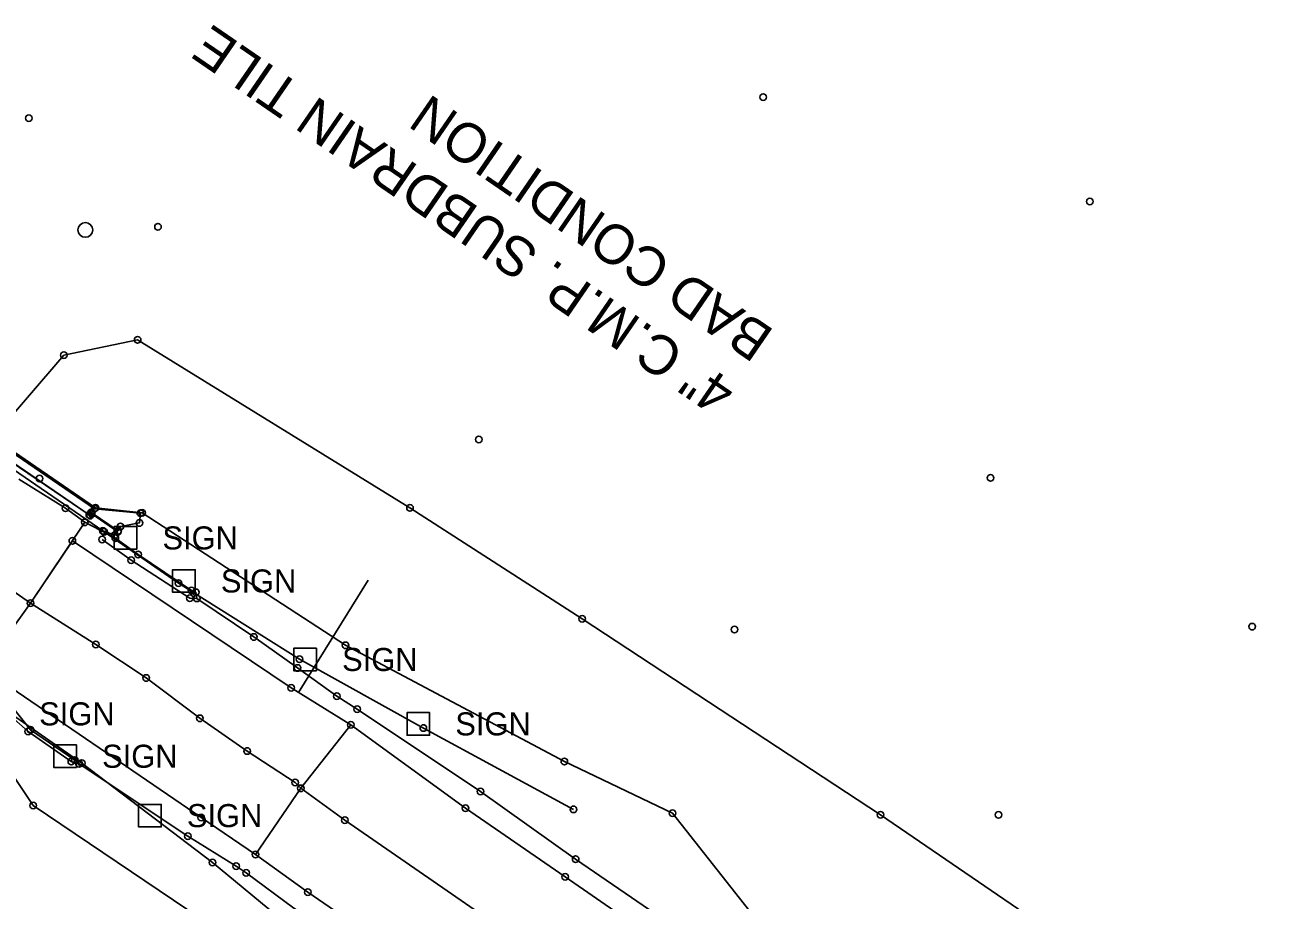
# Model space of a CAD drawing. Extents: x 15502398 to 15534190, y 8766930 to 8782112.
# Drawn here: x 15514954.6 to 15515143.1, y 8779044.6 to 8779177.4 of the extents above; entities that cross this region are included whole.
import ezdxf

# ---------------------------------------------------------------- set-up
doc = ezdxf.new("R2010")
doc.units = 0
for name, color, linetype in [('Bridge', 7, 'Continuous'), ('Default', 7, 'Continuous'), ('EXT_BL', 7, 'Continuous'), ('EXT_C', 7, 'Continuous'), ('EXT_CON', 7, 'Continuous'), ('EXT_CU', 7, 'Continuous'), ('EXT_D', 7, 'Continuous'), ('EXT_EP', 7, 'Continuous'), ('EXT_GU', 7, 'Continuous'), ('EXT_SH', 7, 'Continuous'), ('Roadways', 7, 'Continuous'), ('SurControl', 7, 'Continuous'), ('SurPointsNonDTM', 7, 'Continuous'), ('SurRoadPoints', 7, 'Continuous'), ('SurSurveyPoints', 7, 'Continuous'), ('Text', 7, 'Continuous')]:
    doc.layers.add(name, color=color, linetype=linetype)

msp = doc.modelspace()

# ---------------------------------------------------------------- linework, layer by layer
at = {"layer": 'Bridge'}
for points in [[(15514968.75, 8779100.6), (15514969.07, 8779101.28), (15514971.97, 8779101.81), (15514972.1, 8779103.31), (15514965.17, 8779103.98), (15514897.53, 8779150.29), (15514894.5, 8779156.59), (15514893.48, 8779156.12), (15514893.65, 8779152.05), (15514897.07, 8779149.71), (15514896.88, 8779149.26), (15514922.95, 8779131.4), (15514964.36, 8779103.05), (15514964.63, 8779103.39)], [(15514968.68, 8779100.45), (15514964.72, 8779103.21), (15514964.5, 8779102.92), (15514936.22, 8779122.13), (15514896.74, 8779149.27), (15514896.98, 8779149.65), (15514892.99, 8779152.4), (15514892.59, 8779151.84), (15514894.03, 8779150.29), (15514926.69, 8779127.87), (15514966.4, 8779100.62), (15514968.22, 8779099.97)]]:
    msp.add_lwpolyline(points, close=True, dxfattribs=at)
at = {"layer": 'Default'}
for points in [[(15514887.9, 8779135.92), (15514889.92, 8779134.43), (15514897.71, 8779129.12), (15514905.32, 8779123.86), (15514912.32, 8779119.06), (15514920.38, 8779113.63), (15514928.09, 8779108.21), (15514937.16, 8779102.05), (15514945.69, 8779096.15), (15514950.38, 8779093.11), (15514955.43, 8779089.66)], [(15514946.55, 8779077.26), (15514955.43, 8779089.66), (15514963.69, 8779101.91), (15514960.76, 8779104.04), (15514953.68, 8779108.44)], [(15515037.76, 8779058.36), (15515015.01, 8779070.7), (15514996.24, 8779081.13), (15514977.87, 8779092.69), (15514966.6, 8779100.46)], [(15515014.78, 8779024.91), (15515014.27, 8779023.91), (15514993.78, 8779041.38), (15514983.04, 8779050.29), (15514963.22, 8779065.38), (15514949.32, 8779075.04)]]:
    msp.add_lwpolyline(points, dxfattribs=at)
at = {"layer": 'EXT_BL'}
for points in [[(15514972.37, 8779103.34), (15514965.29, 8779104.12), (15514949.73, 8779114.8), (15514960.51, 8779127.28), (15514971.69, 8779129.58), (15515012.98, 8779104.1), (15515039.09, 8779087.26), (15515084.34, 8779057.54), (15515121.87, 8779031.85), (15515136.34, 8779033.05), (15515158.53, 8779017.54), (15515157.87, 8778999.81), (15515198.39, 8778971.5), (15515237.86, 8778943.51), (15515264.4, 8778926.3), (15515290.1, 8778939.84)], [(15515299.76, 8778934.56), (15515270.88, 8778905.09), (15515228.44, 8778928.8), (15515189.45, 8778954.86), (15515144.22, 8778986.67), (15515149.73, 8779016.04), (15515133.63, 8779026.63), (15515113.74, 8779009.34), (15515065.03, 8779042.26), (15515052.77, 8779057.78), (15515036.39, 8779065.61), (15515003.2, 8779083.25), (15514972.37, 8779103.34)], [(15514924.14, 8779086.4), (15514944.89, 8779074.69), (15514948.37, 8779068.62), (15514949.86, 8779067.79), (15514955.86, 8779058.94), (15515004.6, 8779026.01), (15515051.74, 8778995.2), (15515103.32, 8778961.08), (15515168.39, 8778915.34), (15515228.98, 8778873.25), (15515256.8, 8778852.96)]]:
    msp.add_lwpolyline(points, dxfattribs=at)
at = {"layer": 'EXT_C'}
msp.add_lwpolyline([(15514955.43, 8779089.66), (15514965.34, 8779083.38), (15514972.98, 8779078.29), (15514981.11, 8779072.17), (15514988.29, 8779067.21), (15514995.56, 8779062.44), (15514996.44, 8779061.55), (15515003.11, 8779056.73), (15515023.53, 8779042.6), (15515042.26, 8779029.68), (15515060.1, 8779017.29), (15515079.18, 8779004.26), (15515097.5, 8778991.51), (15515115.64, 8778978.97), (15515133.93, 8778966.45), (15515153.59, 8778952.94), (15515173.34, 8778939.62), (15515192.18, 8778926.74), (15515210.55, 8778914.23), (15515226.89, 8778902.88), (15515245.57, 8778890.09), (15515263, 8778878.15)], dxfattribs=at)
at = {"layer": 'EXT_CON'}
msp.add_lwpolyline([(15514965.17, 8779103.98), (15514972.1, 8779103.31), (15514971.97, 8779101.81), (15514969.07, 8779101.28), (15514968.75, 8779100.6)], dxfattribs=at)
at = {"layer": 'EXT_CU'}
for points in [[(15514980.52, 8779091.29), (15514979.87, 8779091.55), (15514971.75, 8779097.02), (15514968.31, 8779099.52), (15514963.69, 8779101.91)], [(15514962.8, 8779065.26), (15514961.63, 8779065.61), (15514955.09, 8779070.17), (15514950.65, 8779074.06), (15514946.55, 8779077.26)]]:
    msp.add_lwpolyline(points, dxfattribs=at)
at = {"layer": 'EXT_D'}
msp.add_line((15514996.08, 8779076.11), (15515006.64, 8779093.11), dxfattribs=at)
at = {"layer": 'EXT_EP'}
for points in [[(15515004, 8779071.19), (15515021.39, 8779058.52), (15515036.5, 8779048.12), (15515053.54, 8779036.32), (15515073.21, 8779022.82), (15515093.16, 8779009.36), (15515104.5, 8779002.14), (15515104.91, 8779002.59), (15515122.29, 8778991.19), (15515128.53, 8778987.1), (15515146.83, 8778974.46), (15515164.62, 8778962.4), (15515181.23, 8778950.95), (15515199.54, 8778938.45), (15515218.74, 8778925.26), (15515238.6, 8778911.77), (15515263.66, 8778894.48), (15515280.51, 8778882.85)], [(15514989.57, 8779051.49), (15514997.49, 8779045.8), (15515004.92, 8779040.68), (15515013.98, 8779034.36), (15515029.92, 8779023.61), (15515039.85, 8779016.64), (15515057.6, 8779004.48), (15515078.3, 8778990.12), (15515099.03, 8778975.76), (15515113.27, 8778966.3), (15515112.33, 8778964.28), (15515131.99, 8778950.83), (15515154.7, 8778935.27), (15515175.1, 8778921.33), (15515195.6, 8778907.33), (15515215.71, 8778893.41), (15515237.55, 8778878.49), (15515258.35, 8778864.15)]]:
    msp.add_lwpolyline(points, dxfattribs=at)
at = {"layer": 'EXT_GU'}
for points in [[(15514980.66, 8779090.37), (15514979.59, 8779090.39), (15514970.72, 8779096.16), (15514966.3, 8779099.29)], [(15514962.8, 8779065.26), (15514962.15, 8779065.84), (15514955.44, 8779070.43), (15514951.34, 8779075.58), (15514949.87, 8779076.25)]]:
    msp.add_lwpolyline(points, dxfattribs=at)
at = {"layer": 'EXT_SH'}
for points in [[(15514980.52, 8779091.29), (15514980.66, 8779090.37), (15514989.32, 8779084.51), (15514995.93, 8779079.81), (15515001.88, 8779075.54), (15515004.96, 8779073.56), (15515023.67, 8779061.07), (15515038.1, 8779050.82), (15515055.88, 8779038.59), (15515074.84, 8779025.86), (15515095.29, 8779011.9), (15515105.95, 8779004.56), (15515124.43, 8778991.74), (15515129.13, 8778988.68), (15515128.53, 8778987.1)], [(15514962.8, 8779065.26), (15514979.3, 8779054.28), (15514986.62, 8779049.75), (15514988.14, 8779048.72), (15514995.38, 8779043.37), (15515002.91, 8779038.39), (15515011.24, 8779032.4), (15515021.77, 8779025.08), (15515031.37, 8779018.91), (15515037.86, 8779014.18), (15515076.61, 8778987.47), (15515097.47, 8778973.05), (15515111.46, 8778963.29), (15515112.33, 8778964.28)]]:
    msp.add_lwpolyline(points, dxfattribs=at)
at = {"layer": 'Roadways'}
msp.add_lwpolyline([(15515004, 8779071.19), (15514996.44, 8779061.55), (15514989.57, 8779051.49), (15514981.33, 8779057.12), (15514948.28, 8779079.67), (15514955.43, 8779089.66), (15514961.79, 8779099.09), (15514994.98, 8779076.8)], close=True, dxfattribs=at)
at = {"layer": 'SurControl'}
msp.add_circle((15514963.76, 8779146.27), 1.12, dxfattribs=at)
at = {"layer": 'SurPointsNonDTM'}
for centre in [(15514956.82, 8779108.54), (15514960.76, 8779104.04), (15514964.36, 8779103.05), (15514964.5, 8779102.92), (15514964.63, 8779103.39), (15514964.72, 8779103.21), (15514965.17, 8779103.98), (15514972.1, 8779103.31), (15514963.69, 8779101.91), (15514969.07, 8779101.28), (15514971.97, 8779101.81), (15514966.4, 8779100.62), (15514966.6, 8779100.46), (15514968.22, 8779099.97), (15514968.68, 8779100.45), (15514968.68, 8779100.45), (15514968.75, 8779100.6), (15514968.75, 8779100.6), (15514961.79, 8779099.09), (15514977.87, 8779092.69), (15514955.43, 8779089.66), (15514955.43, 8779089.66), (15514955.43, 8779089.66), (15514996.24, 8779081.13), (15514994.98, 8779076.8), (15515004, 8779071.19), (15515004, 8779071.19), (15515015.01, 8779070.7), (15514963.22, 8779065.38), (15514996.44, 8779061.55), (15515037.76, 8779058.36), (15514981.33, 8779057.12), (15514983.04, 8779050.29), (15514989.57, 8779051.49)]:
    msp.add_circle(centre, 0.5, dxfattribs=at)
at = {"layer": 'SurRoadPoints'}
for points in [[(15514969.84, 8779097.83), (15514969.84, 8779097.83), (15514971.56, 8779097.83), (15514971.56, 8779101.25), (15514968.13, 8779101.25), (15514968.13, 8779097.83), (15514969.84, 8779097.83)], [(15514978.7, 8779091.29), (15514978.7, 8779091.29), (15514980.42, 8779091.29), (15514980.42, 8779094.72), (15514976.99, 8779094.72), (15514976.99, 8779091.29), (15514978.7, 8779091.29)], [(15514997.08, 8779079.39), (15514997.08, 8779079.39), (15514998.79, 8779079.39), (15514998.79, 8779082.81), (15514995.37, 8779082.81), (15514995.37, 8779079.39), (15514997.08, 8779079.39)], [(15515014.25, 8779069.61), (15515014.25, 8779069.61), (15515015.96, 8779069.61), (15515015.96, 8779073.04), (15515012.54, 8779073.04), (15515012.54, 8779069.61), (15515014.25, 8779069.61)], [(15514960.69, 8779064.71), (15514960.69, 8779064.71), (15514962.41, 8779064.71), (15514962.41, 8779068.13), (15514958.98, 8779068.13), (15514958.98, 8779064.71), (15514960.69, 8779064.71)], [(15514973.55, 8779055.7), (15514973.55, 8779055.7), (15514975.27, 8779055.7), (15514975.27, 8779059.12), (15514971.84, 8779059.12), (15514971.84, 8779055.7), (15514973.55, 8779055.7)]]:
    msp.add_lwpolyline(points, dxfattribs=at)
at = {"layer": 'SurSurveyPoints'}
for centre in [(15515066.54, 8779166.43), (15514955.19, 8779163.23), (15515116.07, 8779150.59), (15514974.77, 8779146.75), (15514971.69, 8779129.58), (15514960.51, 8779127.28), (15515023.41, 8779114.49), (15515101.02, 8779108.64), (15514965.17, 8779103.98), (15514965.29, 8779104.12), (15514972.1, 8779103.31), (15514972.37, 8779103.34), (15514972.37, 8779103.34), (15515012.98, 8779104.1), (15514963.69, 8779101.91), (15514969.07, 8779101.28), (15514971.97, 8779101.81), (15514966.3, 8779099.29), (15514968.31, 8779099.52), (15514968.75, 8779100.6), (15514970.72, 8779096.16), (15514971.75, 8779097.02), (15514979.59, 8779090.39), (15514979.87, 8779091.55), (15514980.52, 8779091.29), (15514980.52, 8779091.29), (15514980.66, 8779090.37), (15514980.66, 8779090.37), (15514955.43, 8779089.66), (15515039.09, 8779087.26), (15515140.67, 8779086.08), (15514989.32, 8779084.51), (15515062.18, 8779085.63), (15514965.34, 8779083.38), (15515003.2, 8779083.25), (15514995.93, 8779079.81), (15514972.98, 8779078.29), (15515001.88, 8779075.54), (15515004.96, 8779073.56), (15514981.11, 8779072.17), (15515004, 8779071.19), (15514955.09, 8779070.17), (15514955.44, 8779070.43), (15514988.29, 8779067.21), (15514961.63, 8779065.61), (15514962.15, 8779065.84), (15514962.8, 8779065.26), (15514962.8, 8779065.26), (15514962.8, 8779065.26), (15515036.39, 8779065.61), (15514995.56, 8779062.44), (15514996.44, 8779061.55), (15515023.67, 8779061.07), (15514955.86, 8779058.94), (15515021.39, 8779058.52), (15515052.77, 8779057.78), (15515003.11, 8779056.73), (15515084.34, 8779057.54), (15515102.23, 8779057.51), (15514979.3, 8779054.28), (15514989.57, 8779051.49), (15515038.1, 8779050.82), (15514986.62, 8779049.75), (15514988.14, 8779048.72), (15515036.5, 8779048.12), (15514997.49, 8779045.8)]:
    msp.add_circle(centre, 0.5, dxfattribs=at)

# ---------------------------------------------------------------- texts
at = {"layer": 'SurRoadPoints'}
for p in [(15514975.45, 8779097.79), (15514984.31, 8779091.26), (15515002.69, 8779079.35), (15514956.76, 8779071.1), (15515019.86, 8779069.58), (15514966.3, 8779064.67), (15514979.16, 8779055.66)]:
    msp.add_text('SIGN', height=3.498, dxfattribs=at).set_placement(p)
at = {"layer": 'Text'}
for s, p in [('4" C.M.P. SUBDRAIN TILE', (15515062.76, 8779122.68)), ('BAD CONDITION', (15515068.42, 8779130.92))]:
    msp.add_text(s, height=6, rotation=145.4923, dxfattribs=at).set_placement(p)

doc.saveas('drawing.dxf')
